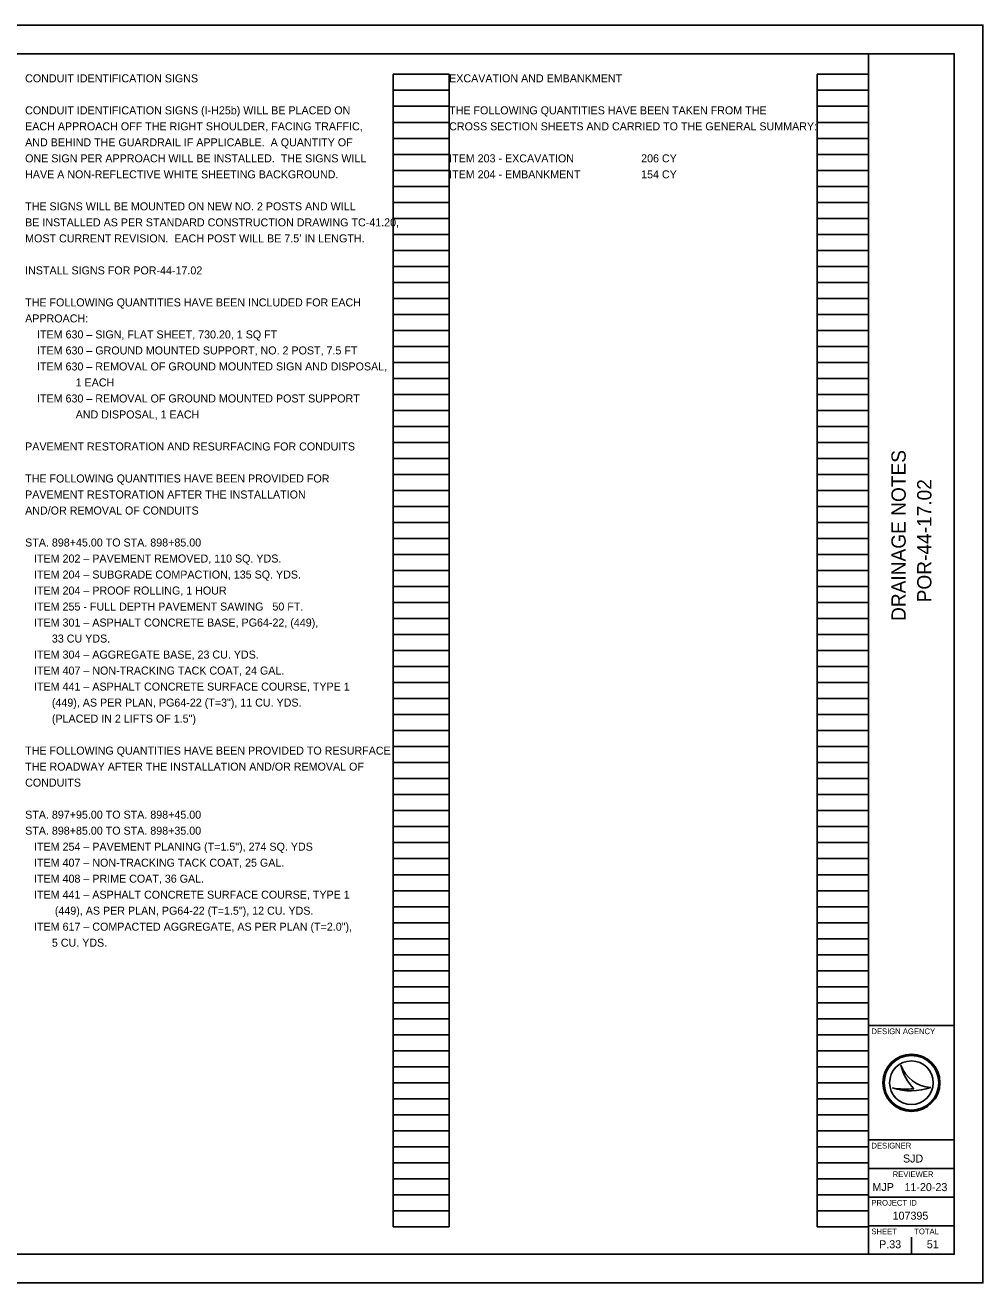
# Model space of a CAD drawing. Extents: x 0 to 34, y 0 to 22.
# Drawn here: x 17.24 to 34, y 0 to 22 of the extents above; entities that cross this region are included whole.
import ezdxf

# ---------------------------------------------------------------- set-up
doc = ezdxf.new("R2010")
doc.units = 0
for name, color, linetype in [('SH_Border', 7, 'Continuous'), ('SH_Cut_Line', 7, 'Continuous'), ('SH_Data', 7, 'Continuous'), ('SH_Text', 7, 'Continuous')]:
    doc.layers.add(name, color=color, linetype=linetype)

msp = doc.modelspace()

# ---------------------------------------------------------------- linework, layer by layer
at = {"layer": 'SH_Border'}
for p, q in [((32, 0.5), (32, 21.5)), ((32, 4.5), (33.5, 4.5)), ((32, 2.5), (33.5, 2.5)), ((32, 2), (33.5, 2)), ((32, 1.5), (33.5, 1.5)), ((32, 1), (33.5, 1))]:
    msp.add_line(p, q, dxfattribs=at)
msp.add_lwpolyline([(1.5, 21.5), (33.5, 21.5), (33.5, 0.5), (1.5, 0.5)], close=True, dxfattribs=at)
at = {"layer": 'SH_Cut_Line'}
msp.add_lwpolyline([(0, 0), (34, 0), (34, 22), (0, 22)], close=True, dxfattribs=at)
at = {"layer": 'SH_Data'}
for p, q in [((23.68, 0.98), (23.68, 21.14)), ((23.68, 21.14), (24.66, 21.14)), ((24.66, 0.98), (24.66, 21.14)), ((31.1, 0.98), (31.1, 21.14)), ((31.1, 21.14), (32, 21.14)), ((32, 0.98), (32, 21.14)), ((23.68, 20.86), (24.66, 20.86)), ((31.1, 20.86), (32, 20.86)), ((23.68, 20.58), (24.66, 20.58)), ((31.1, 20.58), (32, 20.58)), ((23.68, 20.3), (24.66, 20.3)), ((31.1, 20.3), (32, 20.3)), ((23.68, 20.02), (24.66, 20.02)), ((31.1, 20.02), (32, 20.02)), ((23.68, 19.74), (24.66, 19.74)), ((31.1, 19.74), (32, 19.74)), ((23.68, 19.46), (24.66, 19.46)), ((31.1, 19.46), (32, 19.46)), ((23.68, 19.18), (24.66, 19.18)), ((31.1, 19.18), (32, 19.18)), ((23.68, 18.9), (24.66, 18.9)), ((31.1, 18.9), (32, 18.9)), ((23.68, 18.62), (24.66, 18.62)), ((31.1, 18.62), (32, 18.62)), ((23.68, 18.34), (24.66, 18.34)), ((31.1, 18.34), (32, 18.34)), ((23.68, 18.06), (24.66, 18.06)), ((31.1, 18.06), (32, 18.06)), ((23.68, 17.78), (24.66, 17.78)), ((31.1, 17.78), (32, 17.78)), ((23.68, 17.5), (24.66, 17.5)), ((31.1, 17.5), (32, 17.5)), ((23.68, 17.22), (24.66, 17.22)), ((31.1, 17.22), (32, 17.22)), ((23.68, 16.94), (24.66, 16.94)), ((31.1, 16.94), (32, 16.94)), ((23.68, 16.66), (24.66, 16.66)), ((31.1, 16.66), (32, 16.66)), ((23.68, 16.38), (24.66, 16.38)), ((31.1, 16.38), (32, 16.38)), ((23.68, 16.1), (24.66, 16.1)), ((31.1, 16.1), (32, 16.1)), ((23.68, 15.82), (24.66, 15.82)), ((31.1, 15.82), (32, 15.82)), ((23.68, 15.54), (24.66, 15.54)), ((31.1, 15.54), (32, 15.54)), ((23.68, 15.26), (24.66, 15.26)), ((31.1, 15.26), (32, 15.26)), ((23.68, 14.98), (24.66, 14.98)), ((31.1, 14.98), (32, 14.98)), ((23.68, 14.7), (24.66, 14.7)), ((31.1, 14.7), (32, 14.7)), ((23.68, 14.42), (24.66, 14.42)), ((31.1, 14.42), (32, 14.42)), ((23.68, 14.14), (24.66, 14.14)), ((31.1, 14.14), (32, 14.14)), ((23.68, 13.86), (24.66, 13.86)), ((31.1, 13.86), (32, 13.86)), ((23.68, 13.58), (24.66, 13.58)), ((31.1, 13.58), (32, 13.58)), ((23.68, 13.3), (24.66, 13.3)), ((31.1, 13.3), (32, 13.3)), ((23.68, 13.02), (24.66, 13.02)), ((31.1, 13.02), (32, 13.02)), ((23.68, 12.74), (24.66, 12.74)), ((31.1, 12.74), (32, 12.74)), ((23.68, 12.46), (24.66, 12.46)), ((31.1, 12.46), (32, 12.46)), ((23.68, 12.18), (24.66, 12.18)), ((31.1, 12.18), (32, 12.18)), ((23.68, 11.9), (24.66, 11.9)), ((31.1, 11.9), (32, 11.9)), ((23.68, 11.62), (24.66, 11.62)), ((31.1, 11.62), (32, 11.62)), ((23.68, 11.34), (24.66, 11.34)), ((31.1, 11.34), (32, 11.34)), ((23.68, 11.06), (24.66, 11.06)), ((31.1, 11.06), (32, 11.06)), ((23.68, 10.78), (24.66, 10.78)), ((31.1, 10.78), (32, 10.78)), ((23.68, 10.5), (24.66, 10.5)), ((31.1, 10.5), (32, 10.5)), ((23.68, 10.22), (24.66, 10.22)), ((31.1, 10.22), (32, 10.22)), ((23.68, 9.94), (24.66, 9.94)), ((31.1, 9.94), (32, 9.94)), ((23.68, 9.66), (24.66, 9.66)), ((31.1, 9.66), (32, 9.66)), ((23.68, 9.38), (24.66, 9.38)), ((31.1, 9.38), (32, 9.38)), ((23.68, 9.1), (24.66, 9.1)), ((31.1, 9.1), (32, 9.1)), ((23.68, 8.82), (24.66, 8.82)), ((31.1, 8.82), (32, 8.82)), ((23.68, 8.54), (24.66, 8.54)), ((31.1, 8.54), (32, 8.54)), ((23.68, 8.26), (24.66, 8.26)), ((31.1, 8.26), (32, 8.26)), ((23.68, 7.98), (24.66, 7.98)), ((31.1, 7.98), (32, 7.98)), ((23.68, 7.7), (24.66, 7.7)), ((31.1, 7.7), (32, 7.7)), ((23.68, 7.42), (24.66, 7.42)), ((31.1, 7.42), (32, 7.42)), ((23.68, 7.14), (24.66, 7.14)), ((31.1, 7.14), (32, 7.14)), ((23.68, 6.86), (24.66, 6.86)), ((31.1, 6.86), (32, 6.86)), ((23.68, 6.58), (24.66, 6.58)), ((31.1, 6.58), (32, 6.58)), ((23.68, 6.3), (24.66, 6.3)), ((31.1, 6.3), (32, 6.3)), ((23.68, 6.02), (24.66, 6.02)), ((31.1, 6.02), (32, 6.02)), ((23.68, 5.74), (24.66, 5.74)), ((31.1, 5.74), (32, 5.74)), ((23.68, 5.46), (24.66, 5.46)), ((31.1, 5.46), (32, 5.46)), ((23.68, 5.18), (24.66, 5.18)), ((31.1, 5.18), (32, 5.18)), ((23.68, 4.9), (24.66, 4.9)), ((31.1, 4.9), (32, 4.9)), ((23.68, 4.62), (24.66, 4.62)), ((31.1, 4.62), (32, 4.62)), ((23.68, 4.34), (24.66, 4.34)), ((31.1, 4.34), (32, 4.34)), ((23.68, 4.06), (24.66, 4.06)), ((31.1, 4.06), (32, 4.06)), ((23.68, 3.78), (24.66, 3.78)), ((31.1, 3.78), (32, 3.78)), ((32.567, 3.81), (32.567, 3.81)), ((23.68, 3.5), (24.66, 3.5)), ((31.1, 3.5), (32, 3.5)), ((32.417, 3.41), (32.417, 3.41)), ((32.75, 3.5), (32.75, 3.5)), ((33.087, 3.419), (33.087, 3.419)), ((23.68, 3.22), (24.66, 3.22)), ((31.1, 3.22), (32, 3.22)), ((23.68, 2.94), (24.66, 2.94)), ((31.1, 2.94), (32, 2.94)), ((23.68, 2.66), (24.66, 2.66)), ((31.1, 2.66), (32, 2.66)), ((23.68, 2.38), (24.66, 2.38)), ((31.1, 2.38), (32, 2.38)), ((23.68, 2.1), (24.66, 2.1)), ((31.1, 2.1), (32, 2.1)), ((23.68, 1.82), (24.66, 1.82)), ((31.1, 1.82), (32, 1.82)), ((23.68, 1.54), (24.66, 1.54)), ((31.1, 1.54), (32, 1.54)), ((23.68, 1.26), (24.66, 1.26)), ((31.1, 1.26), (32, 1.26)), ((23.68, 0.98), (24.66, 0.98)), ((31.1, 0.98), (32, 0.98)), ((32.375, 0.675), (32.375, 0.675)), ((32.75, 0.5), (32.75, 0.8))]:
    msp.add_line(p, q, dxfattribs=at)
for radius in [0.5, 0.477, 0.477, 0.382]:
    msp.add_circle((32.75, 3.5), radius, dxfattribs=at)
for centre, radius, start, end in [((33.116, 3.998), 0.58, 198.9257, 198.9319), ((33.347, 3.97), 0.796, 191.6379, 191.6421), ((33.116, 3.998), 0.58, 198.9319, 267.1657), ((33.347, 3.97), 0.796, 191.6421, 226.0947), ((32.739, 4.37), 1.013, 251.4576, 290.0832), ((32.648, 4.654), 1.266, 259.4964, 259.4995), ((32.739, 4.37), 1.013, 251.4527, 251.4576), ((32.648, 4.654), 1.266, 259.4995, 276.6672)]:
    msp.add_arc(centre, radius, start, end, dxfattribs=at)

# ---------------------------------------------------------------- texts
for s, p in [('DRAINAGE NOTES', (32.65, 11.578)), ('POR-44-17.02', (33.1, 11.903))]:
    msp.add_text(s, height=0.25, rotation=90, dxfattribs=at).set_placement(p)
for s, height, p in [('DESIGN AGENCY', 0.1, (32.05, 4.35)), ('DESIGNER', 0.1, (32.05, 2.35)), ('SJD', 0.14, (32.602, 2.105)), ('REVIEWER', 0.1, (32.422, 1.85)), ('MJP', 0.14, (32.068, 1.605)), ('11-20-23', 0.14, (32.629, 1.605)), ('PROJECT ID', 0.1, (32.05, 1.35)), ('107395', 0.14, (32.421, 1.105)), ('SHEET', 0.1, (32.05, 0.85)), ('TOTAL', 0.1, (32.8, 0.85)), ('P.33', 0.14, (32.185, 0.605)), ('51', 0.14, (33.019, 0.605))]:
    msp.add_text(s, height=height, dxfattribs=at).set_placement(p)
at = {"layer": 'SH_Text'}
for s, p in [('CONDUIT IDENTIFICATION SIGNS', (17.24, 21)), ('EXCAVATION AND EMBANKMENT', (24.66, 21)), ('CONDUIT IDENTIFICATION SIGNS (I-H25b) WILL BE PLACED ON', (17.24, 20.44)), ('THE FOLLOWING QUANTITIES HAVE BEEN TAKEN FROM THE', (24.66, 20.44)), ('EACH APPROACH OFF THE RIGHT SHOULDER, FACING TRAFFIC,', (17.24, 20.16)), ('CROSS SECTION SHEETS AND CARRIED TO THE GENERAL SUMMARY:', (24.66, 20.16)), ('AND BEHIND THE GUARDRAIL IF APPLICABLE.  A QUANTITY OF', (17.24, 19.88)), ('ONE SIGN PER APPROACH WILL BE INSTALLED.  THE SIGNS WILL', (17.24, 19.6)), ('ITEM 203 - EXCAVATION', (24.66, 19.6)), ('206 CY', (28.02, 19.6)), ('HAVE A NON-REFLECTIVE WHITE SHEETING BACKGROUND.', (17.24, 19.32)), ('ITEM 204 - EMBANKMENT', (24.66, 19.32)), ('154 CY', (28.02, 19.32)), ('THE SIGNS WILL BE MOUNTED ON NEW NO. 2 POSTS AND WILL', (17.24, 18.76)), ('BE INSTALLED AS PER STANDARD CONSTRUCTION DRAWING TC-41.20,', (17.24, 18.48)), ('MOST CURRENT REVISION.  EACH POST WILL BE 7.5’ IN LENGTH.', (17.24, 18.2)), ('INSTALL SIGNS FOR POR-44-17.02', (17.24, 17.64)), ('THE FOLLOWING QUANTITIES HAVE BEEN INCLUDED FOR EACH', (17.24, 17.08)), ('APPROACH:', (17.24, 16.8)), ('    ITEM 630 – SIGN, FLAT SHEET, 730.20, 1 SQ FT', (17.24, 16.52)), ('    ITEM 630 – GROUND MOUNTED SUPPORT, NO. 2 POST, 7.5 FT', (17.24, 16.24)), ('    ITEM 630 – REMOVAL OF GROUND MOUNTED SIGN AND DISPOSAL,', (17.24, 15.96)), ('                 1 EACH', (17.24, 15.68)), ('    ITEM 630 – REMOVAL OF GROUND MOUNTED POST SUPPORT', (17.24, 15.4)), ('                 AND DISPOSAL, 1 EACH', (17.24, 15.12)), ('PAVEMENT RESTORATION AND RESURFACING FOR CONDUITS', (17.24, 14.56)), ('THE FOLLOWING QUANTITIES HAVE BEEN PROVIDED FOR', (17.24, 14)), ('PAVEMENT RESTORATION AFTER THE INSTALLATION', (17.24, 13.72)), ('AND/OR REMOVAL OF CONDUITS', (17.24, 13.44)), ('STA. 898+45.00 TO STA. 898+85.00', (17.24, 12.88)), ('   ITEM 202 – PAVEMENT REMOVED, 110 SQ. YDS.', (17.24, 12.6)), ('   ITEM 204 – SUBGRADE COMPACTION, 135 SQ. YDS.', (17.24, 12.32)), ('   ITEM 204 – PROOF ROLLING, 1 HOUR', (17.24, 12.04)), ('   ITEM 255 - FULL DEPTH PAVEMENT SAWING   50 FT.', (17.24, 11.76)), ('   ITEM 301 – ASPHALT CONCRETE BASE, PG64-22, (449),', (17.24, 11.48)), ('         33 CU YDS.', (17.24, 11.2)), ('   ITEM 304 – AGGREGATE BASE, 23 CU. YDS.', (17.24, 10.92)), ('   ITEM 407 – NON-TRACKING TACK COAT, 24 GAL.', (17.24, 10.64)), ('   ITEM 441 – ASPHALT CONCRETE SURFACE COURSE, TYPE 1', (17.24, 10.36)), ('         (449), AS PER PLAN, PG64-22 (T=3"), 11 CU. YDS.', (17.24, 10.08)), ('         (PLACED IN 2 LIFTS OF 1.5")', (17.24, 9.8)), ('THE FOLLOWING QUANTITIES HAVE BEEN PROVIDED TO RESURFACE', (17.24, 9.24)), ('THE ROADWAY AFTER THE INSTALLATION AND/OR REMOVAL OF', (17.24, 8.96)), ('CONDUITS', (17.24, 8.68)), ('STA. 897+95.00 TO STA. 898+45.00', (17.24, 8.12)), ('STA. 898+85.00 TO STA. 898+35.00', (17.24, 7.84)), ('   ITEM 254 – PAVEMENT PLANING (T=1.5"), 274 SQ. YDS', (17.24, 7.56)), ('   ITEM 407 – NON-TRACKING TACK COAT, 25 GAL.', (17.24, 7.28)), ('   ITEM 408 – PRIME COAT, 36 GAL.', (17.24, 7)), ('   ITEM 441 – ASPHALT CONCRETE SURFACE COURSE, TYPE 1', (17.24, 6.72)), ('          (449), AS PER PLAN, PG64-22 (T=1.5"), 12 CU. YDS.', (17.24, 6.44)), ('   ITEM 617 – COMPACTED AGGREGATE, AS PER PLAN (T=2.0"),', (17.24, 6.16)), ('         5 CU. YDS.', (17.24, 5.88))]:
    msp.add_text(s, height=0.14, dxfattribs=at).set_placement(p)

doc.saveas('drawing.dxf')
